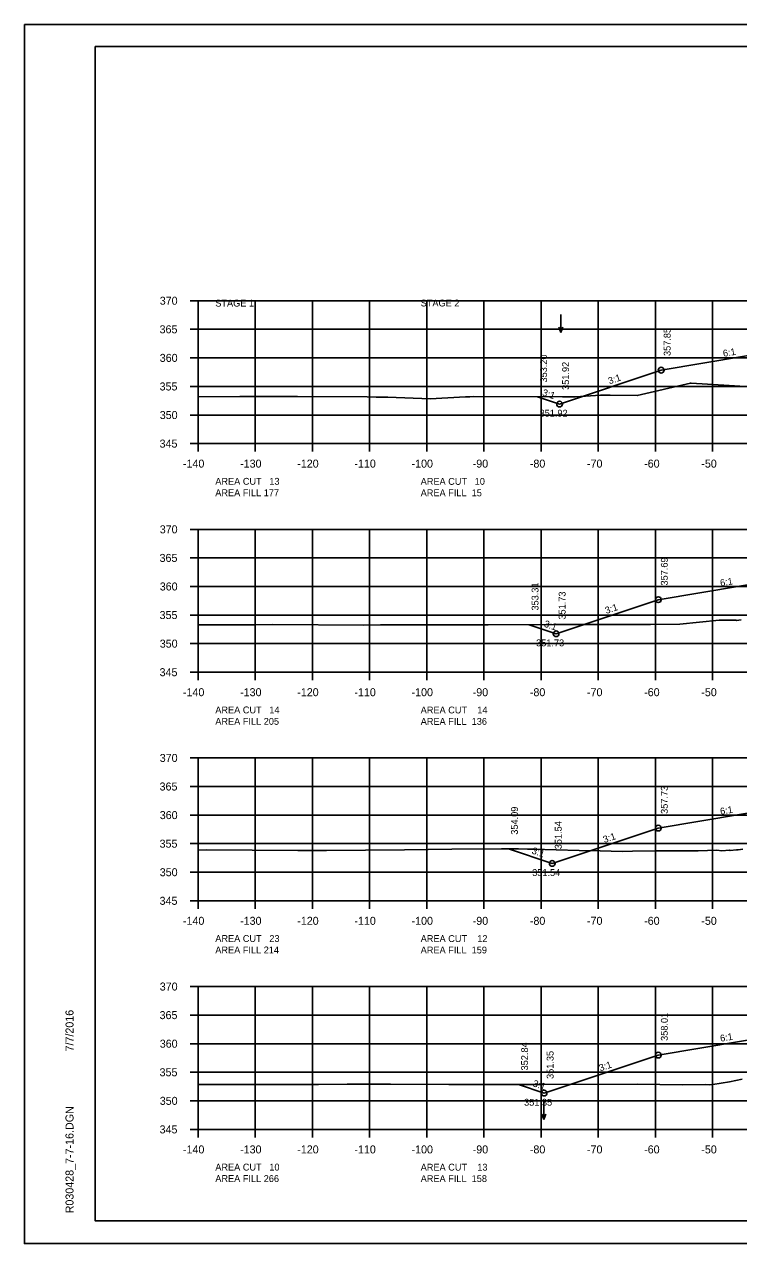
# Model space of a CAD drawing. Extents: x 1374859 to 1376773, y 382242 to 389804.
# Drawn here: x 1375964.2 to 1376089.1, y 386508.5 to 386721.8 of the extents above; entities that cross this region are included whole.
import ezdxf

# ---------------------------------------------------------------- set-up
doc = ezdxf.new("R2010")
doc.units = 0
for name, color, linetype in [('R_Axis', 7, 'Continuous'), ('R_Axis Annot', 7, 'Continuous'), ('R_Border', 7, 'Continuous'), ('R_Exist Surface', 7, 'Continuous'), ('R_Fin Surface', 7, 'Continuous'), ('R_Grid', 7, 'Continuous'), ('R_No Plot', 7, 'Continuous'), ('R_Water Annot', 7, 'Continuous'), ('R_Xsect Elev', 7, 'Continuous'), ('R_Xsect Slope', 7, 'Continuous')]:
    doc.layers.add(name, color=color, linetype=linetype)

msp = doc.modelspace()

# ---------------------------------------------------------------- linework, layer by layer
at = {"layer": 'R_Axis'}
for p, q in [((1375993.17, 386673.48), (1375994.57, 386673.48)), ((1375994.57, 386648.48), (1375994.57, 386673.48)), ((1375993.17, 386668.48), (1375994.57, 386668.48)), ((1375993.17, 386663.48), (1375994.57, 386663.48)), ((1375993.17, 386658.48), (1375994.57, 386658.48)), ((1375993.17, 386653.48), (1375994.57, 386653.48)), ((1375993.17, 386648.48), (1375994.57, 386648.48)), ((1375994.57, 386648.48), (1376274.57, 386648.48)), ((1375994.57, 386647.08), (1375994.57, 386648.48)), ((1376004.57, 386647.08), (1376004.57, 386648.48)), ((1376014.57, 386647.08), (1376014.57, 386648.48)), ((1376024.57, 386647.08), (1376024.57, 386648.48)), ((1376034.57, 386647.08), (1376034.57, 386648.48)), ((1376044.57, 386647.08), (1376044.57, 386648.48)), ((1376054.57, 386647.08), (1376054.57, 386648.48)), ((1376064.57, 386647.08), (1376064.57, 386648.48)), ((1376074.57, 386647.08), (1376074.57, 386648.48)), ((1376084.57, 386647.08), (1376084.57, 386648.48)), ((1375993.17, 386633.48), (1375994.57, 386633.48)), ((1375994.57, 386608.48), (1375994.57, 386633.48)), ((1375993.17, 386628.48), (1375994.57, 386628.48)), ((1375993.17, 386623.48), (1375994.57, 386623.48)), ((1375993.17, 386618.48), (1375994.57, 386618.48)), ((1375993.17, 386613.48), (1375994.57, 386613.48)), ((1375993.17, 386608.48), (1375994.57, 386608.48)), ((1375994.57, 386608.48), (1376274.57, 386608.48)), ((1375994.57, 386607.08), (1375994.57, 386608.48)), ((1376004.57, 386607.08), (1376004.57, 386608.48)), ((1376014.57, 386607.08), (1376014.57, 386608.48)), ((1376024.57, 386607.08), (1376024.57, 386608.48)), ((1376034.57, 386607.08), (1376034.57, 386608.48)), ((1376044.57, 386607.08), (1376044.57, 386608.48)), ((1376054.57, 386607.08), (1376054.57, 386608.48)), ((1376064.57, 386607.08), (1376064.57, 386608.48)), ((1376074.57, 386607.08), (1376074.57, 386608.48)), ((1376084.57, 386607.08), (1376084.57, 386608.48)), ((1375993.17, 386593.48), (1375994.57, 386593.48)), ((1375994.57, 386568.48), (1375994.57, 386593.48)), ((1375993.17, 386588.48), (1375994.57, 386588.48)), ((1375993.17, 386583.48), (1375994.57, 386583.48)), ((1375993.17, 386578.48), (1375994.57, 386578.48)), ((1375993.17, 386573.48), (1375994.57, 386573.48)), ((1375993.17, 386568.48), (1375994.57, 386568.48)), ((1375994.57, 386568.48), (1376274.57, 386568.48)), ((1375994.57, 386567.08), (1375994.57, 386568.48)), ((1376004.57, 386567.08), (1376004.57, 386568.48)), ((1376014.57, 386567.08), (1376014.57, 386568.48)), ((1376024.57, 386567.08), (1376024.57, 386568.48)), ((1376034.57, 386567.08), (1376034.57, 386568.48)), ((1376044.57, 386567.08), (1376044.57, 386568.48)), ((1376054.57, 386567.08), (1376054.57, 386568.48)), ((1376064.57, 386567.08), (1376064.57, 386568.48)), ((1376074.57, 386567.08), (1376074.57, 386568.48)), ((1376084.57, 386567.08), (1376084.57, 386568.48)), ((1375993.17, 386553.48), (1375994.57, 386553.48)), ((1375994.57, 386528.48), (1375994.57, 386553.48)), ((1375993.17, 386548.48), (1375994.57, 386548.48)), ((1375993.17, 386543.48), (1375994.57, 386543.48)), ((1375993.17, 386538.48), (1375994.57, 386538.48)), ((1375993.17, 386533.48), (1375994.57, 386533.48)), ((1375993.17, 386528.48), (1375994.57, 386528.48)), ((1375994.57, 386528.48), (1376274.57, 386528.48)), ((1375994.57, 386527.08), (1375994.57, 386528.48)), ((1376004.57, 386527.08), (1376004.57, 386528.48)), ((1376014.57, 386527.08), (1376014.57, 386528.48)), ((1376024.57, 386527.08), (1376024.57, 386528.48)), ((1376034.57, 386527.08), (1376034.57, 386528.48)), ((1376044.57, 386527.08), (1376044.57, 386528.48)), ((1376054.57, 386527.08), (1376054.57, 386528.48)), ((1376064.57, 386527.08), (1376064.57, 386528.48)), ((1376074.57, 386527.08), (1376074.57, 386528.48)), ((1376084.57, 386527.08), (1376084.57, 386528.48))]:
    msp.add_line(p, q, dxfattribs=at)
at = {"layer": 'R_Border'}
for p, q in [((1375976.57, 386717.94), (1376292.75, 386717.94)), ((1375976.57, 386512.48), (1375976.57, 386717.94)), ((1375976.57, 386512.48), (1375976.57, 386512.48)), ((1376292.75, 386512.48), (1375976.57, 386512.48))]:
    msp.add_line(p, q, dxfattribs=at)
at = {"layer": 'R_Exist Surface'}
for points in [[(1375994.57, 386656.69), (1376001.88, 386656.7), (1376011.96, 386656.71), (1376024.15, 386656.69), (1376025.69, 386656.59), (1376027.78, 386656.59), (1376035.16, 386656.32), (1376041.35, 386656.68), (1376042.1, 386656.69), (1376042.83, 386656.71), (1376058.31, 386656.68), (1376060.61, 386656.68), (1376064.99, 386656.97), (1376066.67, 386656.93), (1376071.41, 386656.88), (1376080.72, 386659.07), (1376080.76, 386659.07), (1376080.76, 386659.08), (1376080.76, 386659.08), (1376080.77, 386659.08), (1376080.78, 386659.08), (1376080.79, 386659.08), (1376080.82, 386659.07), (1376095.05, 386658.17)], [(1375994.57, 386616.79), (1376001.08, 386616.79), (1376004.48, 386616.79), (1376007.66, 386616.8), (1376023.56, 386616.74), (1376026.49, 386616.75), (1376039.46, 386616.77), (1376045.31, 386616.77), (1376056.96, 386616.8), (1376062.19, 386616.8), (1376063.12, 386616.82), (1376073.71, 386616.84), (1376078.84, 386616.86), (1376085.71, 386617.59), (1376085.8, 386617.6), (1376088.36, 386617.57), (1376088.64, 386617.57), (1376088.77, 386617.55), (1376089.57, 386617.62)], [(1375994.57, 386577.37), (1375996.03, 386577.38), (1376012.01, 386577.31), (1376017.03, 386577.28), (1376030.68, 386577.39), (1376038.93, 386577.53), (1376047.67, 386577.59), (1376050.64, 386577.55), (1376052.19, 386577.51), (1376053.18, 386577.53), (1376061.26, 386577.29), (1376064.92, 386577.2), (1376068.76, 386577.12), (1376070.55, 386577.16), (1376074.79, 386577.23), (1376080.46, 386577.25), (1376082.07, 386577.24), (1376085.34, 386577.36), (1376086.19, 386577.24), (1376087.54, 386577.32), (1376087.66, 386577.31), (1376088.76, 386577.39), (1376089.08, 386577.42), (1376089.89, 386577.52)], [(1375994.57, 386536.33), (1376001.62, 386536.34), (1376007.53, 386536.33), (1376015.62, 386536.33), (1376020.64, 386536.39), (1376028.22, 386536.39), (1376038.46, 386536.33), (1376053.72, 386536.31), (1376054.25, 386536.32), (1376054.36, 386536.31), (1376054.87, 386536.32), (1376071.45, 386536.37), (1376079.25, 386536.3), (1376083.4, 386536.33), (1376084.09, 386536.28), (1376084.63, 386536.35), (1376087.52, 386536.79), (1376089.76, 386537.3)]]:
    msp.add_lwpolyline(points, dxfattribs=at)
at = {"layer": 'R_Fin Surface'}
for points in [[(1376053.96, 386656.68), (1376057.81, 386655.4), (1376075.59, 386661.33), (1376090.15, 386663.76), (1376097.59, 386665), (1376105.59, 386665.32), (1376134.59, 386665.9), (1376163.59, 386665.32), (1376171.59, 386665), (1376179.02, 386663.76), (1376193.59, 386661.33), (1376202.74, 386658.28)], [(1376052.47, 386616.79), (1376057.21, 386615.21), (1376075.09, 386621.17), (1376089.65, 386623.6), (1376097.09, 386624.84), (1376105.09, 386625.16), (1376134.59, 386625.75), (1376164.09, 386625.16), (1376172.09, 386624.84), (1376179.52, 386623.6), (1376194.09, 386621.17), (1376208.16, 386616.48), (1376212.24, 386617.84)], [(1376048.86, 386577.57), (1376056.52, 386575.02), (1376075.09, 386581.21), (1376089.65, 386583.63), (1376097.09, 386584.87), (1376105.09, 386585.19), (1376134.59, 386585.78), (1376164.09, 386585.19), (1376172.09, 386584.87), (1376179.52, 386583.64), (1376194.09, 386581.21), (1376209.17, 386576.18), (1376213.06, 386577.48)], [(1376050.63, 386536.32), (1376055.1, 386534.83), (1376075.09, 386541.49), (1376089.65, 386543.92), (1376097.09, 386545.15), (1376105.09, 386545.47), (1376134.59, 386546.06), (1376164.09, 386545.47), (1376172.09, 386545.15), (1376179.52, 386543.92), (1376194.09, 386541.49), (1376210.91, 386535.88), (1376215.89, 386537.54)]]:
    msp.add_lwpolyline(points, dxfattribs=at)
at = {"layer": 'R_Grid'}
for p, q in [((1375994.57, 386673.48), (1376274.57, 386673.48)), ((1375994.57, 386648.48), (1375994.57, 386673.48)), ((1376004.57, 386648.48), (1376004.57, 386673.48)), ((1376014.57, 386648.48), (1376014.57, 386673.48)), ((1376024.57, 386648.48), (1376024.57, 386673.48)), ((1376034.57, 386648.48), (1376034.57, 386673.48)), ((1376044.57, 386648.48), (1376044.57, 386673.48)), ((1376054.57, 386648.48), (1376054.57, 386673.48)), ((1376064.57, 386648.48), (1376064.57, 386673.48)), ((1376074.57, 386648.48), (1376074.57, 386673.48)), ((1376084.57, 386648.48), (1376084.57, 386673.48)), ((1375994.57, 386668.48), (1376274.57, 386668.48)), ((1375994.57, 386663.48), (1376274.57, 386663.48)), ((1375994.57, 386658.48), (1376274.57, 386658.48)), ((1375994.57, 386653.48), (1376274.57, 386653.48)), ((1375994.57, 386648.48), (1376274.57, 386648.48)), ((1375994.57, 386633.48), (1376274.57, 386633.48)), ((1375994.57, 386608.48), (1375994.57, 386633.48)), ((1376004.57, 386608.48), (1376004.57, 386633.48)), ((1376014.57, 386608.48), (1376014.57, 386633.48)), ((1376024.57, 386608.48), (1376024.57, 386633.48)), ((1376034.57, 386608.48), (1376034.57, 386633.48)), ((1376044.57, 386608.48), (1376044.57, 386633.48)), ((1376054.57, 386608.48), (1376054.57, 386633.48)), ((1376064.57, 386608.48), (1376064.57, 386633.48)), ((1376074.57, 386608.48), (1376074.57, 386633.48)), ((1376084.57, 386608.48), (1376084.57, 386633.48)), ((1375994.57, 386628.48), (1376274.57, 386628.48)), ((1375994.57, 386623.48), (1376274.57, 386623.48)), ((1375994.57, 386618.48), (1376274.57, 386618.48)), ((1375994.57, 386613.48), (1376274.57, 386613.48)), ((1375994.57, 386608.48), (1376274.57, 386608.48)), ((1375994.57, 386593.48), (1376274.57, 386593.48)), ((1375994.57, 386568.48), (1375994.57, 386593.48)), ((1376004.57, 386568.48), (1376004.57, 386593.48)), ((1376014.57, 386568.48), (1376014.57, 386593.48)), ((1376024.57, 386568.48), (1376024.57, 386593.48)), ((1376034.57, 386568.48), (1376034.57, 386593.48)), ((1376044.57, 386568.48), (1376044.57, 386593.48)), ((1376054.57, 386568.48), (1376054.57, 386593.48)), ((1376064.57, 386568.48), (1376064.57, 386593.48)), ((1376074.57, 386568.48), (1376074.57, 386593.48)), ((1376084.57, 386568.48), (1376084.57, 386593.48)), ((1375994.57, 386588.48), (1376274.57, 386588.48)), ((1375994.57, 386583.48), (1376274.57, 386583.48)), ((1375994.57, 386578.48), (1376274.57, 386578.48)), ((1375994.57, 386573.48), (1376274.57, 386573.48)), ((1375994.57, 386568.48), (1376274.57, 386568.48)), ((1375994.57, 386553.48), (1376274.57, 386553.48)), ((1375994.57, 386528.48), (1375994.57, 386553.48)), ((1376004.57, 386528.48), (1376004.57, 386553.48)), ((1376014.57, 386528.48), (1376014.57, 386553.48)), ((1376024.57, 386528.48), (1376024.57, 386553.48)), ((1376034.57, 386528.48), (1376034.57, 386553.48)), ((1376044.57, 386528.48), (1376044.57, 386553.48)), ((1376054.57, 386528.48), (1376054.57, 386553.48)), ((1376064.57, 386528.48), (1376064.57, 386553.48)), ((1376074.57, 386528.48), (1376074.57, 386553.48)), ((1376084.57, 386528.48), (1376084.57, 386553.48)), ((1375994.57, 386548.48), (1376274.57, 386548.48)), ((1375994.57, 386543.48), (1376274.57, 386543.48)), ((1375994.57, 386538.48), (1376274.57, 386538.48)), ((1375994.57, 386533.48), (1376274.57, 386533.48)), ((1375994.57, 386528.48), (1376274.57, 386528.48))]:
    msp.add_line(p, q, dxfattribs=at)
at = {"layer": 'R_No Plot'}
for p, q in [((1375964.17, 386721.83), (1376297.5, 386721.83)), ((1375964.17, 386508.5), (1376297.5, 386508.5))]:
    msp.add_line(p, q, dxfattribs=at)
for points in [[(1375964.16, 386721.83), (1376297.5, 386721.83), (1376297.5, 386508.5), (1375964.16, 386508.5)], [(1376210.49, 386717.94), (1376210.49, 386708.06), (1376246.22, 386708.06), (1376246.22, 386705.14), (1376269.42, 386705.14), (1376269.42, 386680.81), (1376292.75, 386680.81), (1376292.75, 386512.48), (1375976.57, 386512.48), (1375976.57, 386717.94)]]:
    msp.add_lwpolyline(points, close=True, dxfattribs=at)
for centre in [(1376075.59, 386661.33), (1376057.81, 386655.4), (1376075.09, 386621.17), (1376057.21, 386615.21), (1376075.09, 386581.21), (1376056.52, 386575.02), (1376075.09, 386541.49), (1376055.1, 386534.83)]:
    msp.add_circle(centre, 0.5, dxfattribs=at)
at = {"layer": 'R_Water Annot'}
for p, q in [((1376058.05, 386671.06), (1376058.05, 386667.91)), ((1376058.05, 386667.91), (1376057.7, 386668.88)), ((1376058.05, 386667.91), (1376058.4, 386668.88)), ((1376055.06, 386533.35), (1376055.06, 386530.21)), ((1376055.06, 386530.21), (1376054.71, 386531.17)), ((1376055.06, 386530.21), (1376055.41, 386531.17))]:
    msp.add_line(p, q, dxfattribs=at)

# ---------------------------------------------------------------- texts
at = {"layer": 'R_Axis Annot'}
for s, height, p in [('370', 1.4, (1375987.85, 386672.78)), ('365', 1.4, (1375987.82, 386667.78)), ('360', 1.4, (1375987.85, 386662.78)), ('355', 1.4, (1375987.82, 386657.78)), ('350', 1.4, (1375987.85, 386652.78)), ('345', 1.4, (1375987.82, 386647.78)), ('-140', 1.4, (1375991.91, 386644.28)), ('-130', 1.4, (1376001.91, 386644.28)), ('-120', 1.4, (1376011.91, 386644.28)), ('-110', 1.4, (1376021.91, 386644.28)), ('-100', 1.4, (1376031.91, 386644.28)), ('-90', 1.4, (1376042.61, 386644.28)), ('-80', 1.4, (1376052.61, 386644.28)), ('-70', 1.4, (1376062.61, 386644.28)), ('-60', 1.4, (1376072.61, 386644.28)), ('-50', 1.4, (1376082.61, 386644.28)), ('AREA CUT   13', 1.2, (1375997.57, 386641.28)), ('AREA CUT   10', 1.2, (1376033.51, 386641.27)), ('AREA FILL 177', 1.2, (1375997.57, 386639.28)), ('AREA FILL  15', 1.2, (1376033.51, 386639.27)), ('370', 1.4, (1375987.85, 386632.78)), ('365', 1.4, (1375987.82, 386627.78)), ('360', 1.4, (1375987.85, 386622.78)), ('355', 1.4, (1375987.82, 386617.78)), ('350', 1.4, (1375987.85, 386612.78)), ('345', 1.4, (1375987.82, 386607.78)), ('-140', 1.4, (1375991.91, 386604.28)), ('-130', 1.4, (1376001.91, 386604.28)), ('-120', 1.4, (1376011.91, 386604.28)), ('-110', 1.4, (1376021.91, 386604.28)), ('-100', 1.4, (1376031.91, 386604.28)), ('-90', 1.4, (1376042.61, 386604.28)), ('-80', 1.4, (1376052.61, 386604.28)), ('-70', 1.4, (1376062.61, 386604.28)), ('-60', 1.4, (1376072.61, 386604.28)), ('-50', 1.4, (1376082.61, 386604.28)), ('AREA CUT   14', 1.2, (1375997.57, 386601.28)), ('AREA CUT    14', 1.2, (1376033.51, 386601.27)), ('AREA FILL 205', 1.2, (1375997.57, 386599.28)), ('AREA FILL  136', 1.2, (1376033.51, 386599.27)), ('370', 1.4, (1375987.85, 386592.78)), ('365', 1.4, (1375987.82, 386587.78)), ('360', 1.4, (1375987.85, 386582.78)), ('355', 1.4, (1375987.82, 386577.78)), ('350', 1.4, (1375987.85, 386572.78)), ('345', 1.4, (1375987.82, 386567.78)), ('-140', 1.4, (1375991.91, 386564.28)), ('-130', 1.4, (1376001.91, 386564.28)), ('-120', 1.4, (1376011.91, 386564.28)), ('-110', 1.4, (1376021.91, 386564.28)), ('-100', 1.4, (1376031.91, 386564.28)), ('-90', 1.4, (1376042.61, 386564.28)), ('-80', 1.4, (1376052.61, 386564.28)), ('-70', 1.4, (1376062.61, 386564.28)), ('-60', 1.4, (1376072.61, 386564.28)), ('-50', 1.4, (1376082.61, 386564.28)), ('AREA CUT   23', 1.2, (1375997.57, 386561.28)), ('AREA CUT    12', 1.2, (1376033.51, 386561.27)), ('AREA FILL 214', 1.2, (1375997.57, 386559.28)), ('AREA FILL  159', 1.2, (1376033.51, 386559.27)), ('370', 1.4, (1375987.85, 386552.78)), ('365', 1.4, (1375987.82, 386547.78)), ('360', 1.4, (1375987.85, 386542.78)), ('355', 1.4, (1375987.82, 386537.78)), ('350', 1.4, (1375987.85, 386532.78)), ('345', 1.4, (1375987.82, 386527.78)), ('-140', 1.4, (1375991.91, 386524.28)), ('-130', 1.4, (1376001.91, 386524.28)), ('-120', 1.4, (1376011.91, 386524.28)), ('-110', 1.4, (1376021.91, 386524.28)), ('-100', 1.4, (1376031.91, 386524.28)), ('-90', 1.4, (1376042.61, 386524.28)), ('-80', 1.4, (1376052.61, 386524.28)), ('-70', 1.4, (1376062.61, 386524.28)), ('-60', 1.4, (1376072.61, 386524.28)), ('-50', 1.4, (1376082.61, 386524.28)), ('AREA CUT   10', 1.2, (1375997.57, 386521.28)), ('AREA CUT    13', 1.2, (1376033.51, 386521.27)), ('AREA FILL 266', 1.2, (1375997.57, 386519.28)), ('AREA FILL  158', 1.2, (1376033.51, 386519.27))]:
    msp.add_text(s, height=height, dxfattribs=at).set_placement(p)
for s, p in [('STAGE 1', (1375997.57, 386672.46)), ('STAGE 2', (1376033.51, 386672.48))]:
    msp.add_text(s, height=1.2, rotation=360, dxfattribs=at).set_placement(p)
at = {"layer": 'R_Border'}
for s, p in [('7/7/2016', (1375972.76, 386542.12)), ('R030428_7-7-16.DGN', (1375972.76, 386513.8))]:
    msp.add_text(s, height=1.4, rotation=90, dxfattribs=at).set_placement(p)
at = {"layer": 'R_Xsect Elev'}
for s, p in [('357.85', (1376077.24, 386663.81)), ('353.20', (1376055.62, 386659.17)), ('351.92', (1376059.46, 386657.88)), ('357.69', (1376076.74, 386623.65)), ('353.31', (1376054.12, 386619.27)), ('351.73', (1376058.86, 386617.69)), ('357.73', (1376076.74, 386583.69)), ('354.09', (1376050.52, 386580.05)), ('351.54', (1376058.18, 386577.5)), ('358.01', (1376076.74, 386543.97)), ('352.84', (1376052.29, 386538.8)), ('351.35', (1376056.76, 386537.31))]:
    msp.add_text(s, height=1.2, rotation=90, dxfattribs=at).set_placement(p)
for s, p in [('351.92', (1376054.31, 386653.2)), ('351.73', (1376053.71, 386613.01)), ('351.54', (1376053.02, 386572.82)), ('351.35', (1376051.6, 386532.63))]:
    msp.add_text(s, height=1.2, dxfattribs=at).set_placement(p)
at = {"layer": 'R_Xsect Slope'}
for s, rotation, p in [('6:1', 9.4642, (1376086.5, 386663.66)), ('3:1', 18.4349, (1376066.54, 386658.84)), ('3:1', 341.5651, (1376054.68, 386656.93)), ('6:1', 9.4642, (1376086, 386623.5)), ('3:1', 18.4349, (1376065.99, 386618.67)), ('3:1', 341.5651, (1376054.99, 386616.47)), ('6:1', 9.4642, (1376086, 386583.53)), ('3:1', 18.4349, (1376065.65, 386578.59)), ('3:1', 341.5651, (1376052.85, 386576.77)), ('6:1', 9.4642, (1376086, 386543.81)), ('3:1', 18.4349, (1376064.94, 386538.63)), ('3:1', 341.5651, (1376053.02, 386536.05))]:
    msp.add_text(s, height=1.2, rotation=rotation, dxfattribs=at).set_placement(p)

doc.saveas('drawing.dxf')
